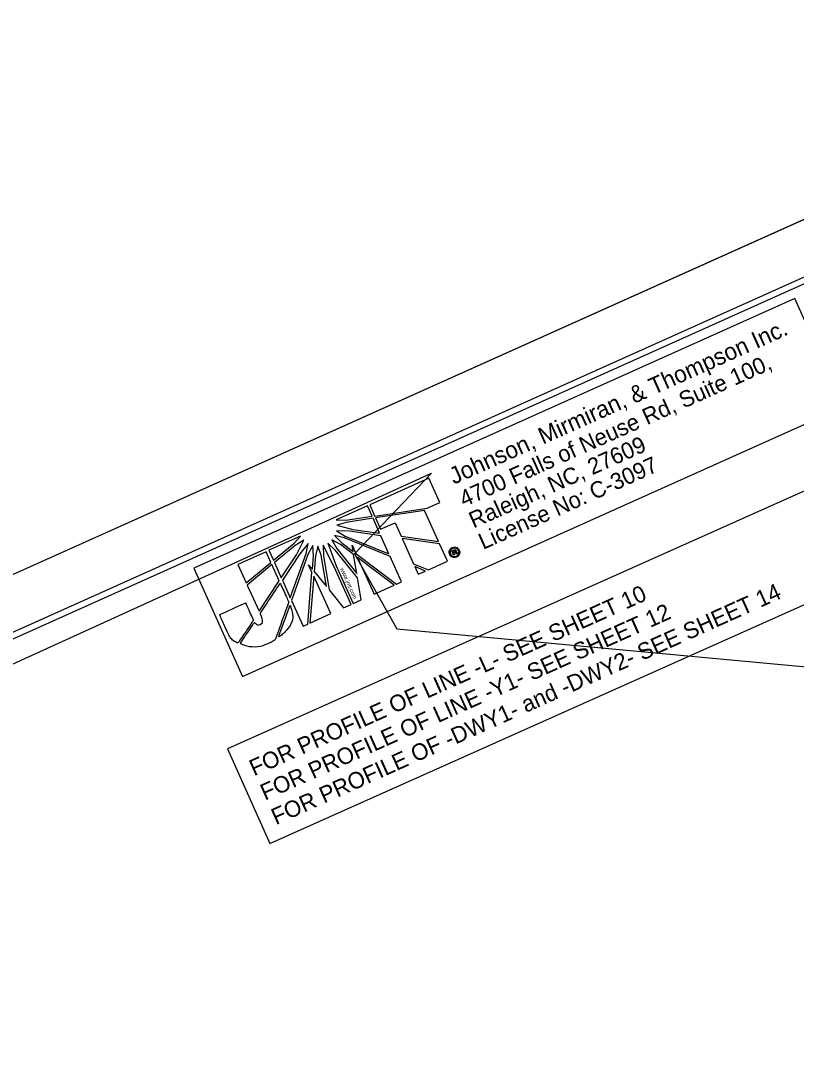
# Model space of a CAD drawing. Extents: x 553939 to 555925, y 502653 to 504347.
# Drawn here: x 554953.8 to 555283.4, y 503904.2 to 504346.6 of the extents above; entities that cross this region are included whole.
import ezdxf

# ---------------------------------------------------------------- set-up
doc = ezdxf.new("R2010")
doc.units = 0
for name, color, linetype in [('Prop Horizontal Alignment Curve and Spiral Data', 7, 'Continuous'), ('Prop Horizontal Alignment Direction Label', 7, 'Continuous'), ('Prop SS Cut Line', 7, 'Continuous'), ('Prop SS Fill Line', 7, 'Continuous'), ('Prop SS Transition Line', 7, 'Continuous'), ('Scratch_Level_9', 7, 'Continuous'), ('Sheet Clip Boundary CELL', 7, 'Continuous')]:
    doc.layers.add(name, color=color, linetype=linetype)

msp = doc.modelspace()

# ---------------------------------------------------------------- linework, layer by layer
at = {"layer": 'Prop Horizontal Alignment Curve and Spiral Data'}
msp.add_lwpolyline([(555041.64, 504036.97), (555059.67, 503996.82), (555333.29, 504119.14), (555315.26, 504159.3), (555041.64, 504036.97)], dxfattribs=at)
at = {"layer": 'Prop Horizontal Alignment Direction Label'}
msp.add_lwpolyline([(555474.87, 504346.62), (553938.64, 503656.8), (554389.23, 502653.32), (555925.47, 503343.14)], close=True, dxfattribs=at)
at = {"layer": 'Prop SS Cut Line'}
msp.add_lwpolyline([(555469.6, 504316.85), (554101.23, 503702.4), (554531.34, 502744.54), (555899.72, 503358.98)], close=True, dxfattribs=at)
at = {"layer": 'Prop SS Fill Line'}
msp.add_lwpolyline([(555479.96, 504324.29), (553959.7, 503641.65), (554391.9, 502679.13), (555912.16, 503361.78)], close=True, dxfattribs=at)
at = {"layer": 'Prop SS Transition Line'}
for p, q in [((555127.25, 504152.07), (555102.12, 504140.76)), ((555131.88, 504141.78), (555127.25, 504152.07)), ((555126.54, 504139.37), (555131.88, 504141.78)), ((555101.22, 504140.29), (555087.94, 504134.38)), ((555103.16, 504135.99), (555101.22, 504140.29)), ((555102.12, 504140.76), (555104.2, 504136.15)), ((555104.26, 504136.01), (555126.54, 504139.37)), ((555125.48, 504138.35), (555104.58, 504135.3)), ((555131.42, 504125.16), (555125.48, 504138.35)), ((555087.94, 504134.38), (555092.01, 504134.31)), ((555092.06, 504133.29), (555088.16, 504132.11)), ((555092.01, 504134.31), (555103.16, 504135.99)), ((555103.57, 504135.08), (555092.06, 504133.29)), ((555106.34, 504128.72), (555103.57, 504135.08)), ((555104.2, 504136.15), (555104.26, 504136.01)), ((555104.58, 504135.3), (555104.62, 504135.22)), ((555104.62, 504135.22), (555106.78, 504130.41)), ((555106.78, 504130.41), (555112.92, 504133.17)), ((555112.92, 504133.17), (555115.5, 504127.43)), ((555087.95, 504129.78), (555091.74, 504127.53)), ((555093.6, 504129.55), (555087.95, 504129.78)), ((555088.16, 504132.11), (555095.02, 504130.26)), ((555106.82, 504127.65), (555093.6, 504129.55)), ((555095.02, 504130.26), (555106.34, 504128.72)), ((555072.72, 504127.53), (555059.27, 504121.47)), ((555061.2, 504117.19), (555069.97, 504124.46)), ((555069.97, 504124.46), (555072.72, 504127.53)), ((555074.08, 504125.77), (555070.39, 504123.54)), ((555070.94, 504119.52), (555074.08, 504125.77)), ((555075.9, 504124.36), (555072.38, 504120)), ((555075.05, 504120.09), (555075.9, 504124.36)), ((555084.31, 504124.49), (555087.94, 504114.79)), ((555087.61, 504121.37), (555084.31, 504124.49)), ((555085.98, 504125.88), (555088.1, 504122.24)), ((555089.66, 504123.89), (555085.98, 504125.88)), ((555087.2, 504127.71), (555090.38, 504124.54)), ((555091.47, 504126.7), (555087.2, 504127.71)), ((555090.38, 504124.54), (555095.08, 504120.95)), ((555110.82, 504118.76), (555091.47, 504126.7)), ((555091.74, 504127.53), (555110.26, 504120)), ((555110.26, 504120), (555106.82, 504127.65)), ((555115.5, 504127.43), (555131.42, 504125.16)), ((555115.94, 504126.45), (555120.76, 504115.76)), ((555131.84, 504124.23), (555115.94, 504126.45)), ((555135.17, 504116.82), (555131.84, 504124.23)), ((555058.05, 504120.85), (555046.1, 504115.47)), ((555060.13, 504116.24), (555058.05, 504120.85)), ((555059.27, 504121.47), (555061.2, 504117.19)), ((555070.39, 504123.54), (555061.61, 504116.27)), ((555064.53, 504109.8), (555070.94, 504119.52)), ((555072.38, 504120), (555065, 504108.75)), ((555068.35, 504101.3), (555075.05, 504120.09)), ((555075.86, 504119.67), (555068.92, 504100.04)), ((555077.93, 504123.54), (555075.86, 504119.67)), ((555078.19, 504119.06), (555077.93, 504123.54)), ((555080.12, 504123.25), (555079.13, 504119.14)), ((555081.45, 504119.41), (555080.12, 504123.25)), ((555087.09, 504114.41), (555082.34, 504123.6)), ((555082.34, 504123.6), (555082.42, 504119.04)), ((555096.94, 504109.81), (555087.61, 504121.37)), ((555088.1, 504122.24), (555096.63, 504111.56)), ((555095.27, 504119.68), (555089.66, 504123.89)), ((555095.08, 504120.95), (555094.63, 504123.59)), ((555094.63, 504123.59), (555096.2, 504120.1)), ((555096.63, 504111.56), (555095.27, 504119.68)), ((555096.2, 504120.1), (555113.54, 504107.08)), ((555136.99, 504121.19), (555137.74, 504121.53)), ((555137.81, 504119.36), (555136.99, 504121.19)), ((555137.25, 504122.6), (555137.42, 504122.22)), ((555137.42, 504122.22), (555137.25, 504122.6)), ((555137.89, 504121.18), (555137.56, 504121.03)), ((555137.56, 504121.03), (555137.76, 504120.59)), ((555137.74, 504121.53), (555137.85, 504121.58)), ((555137.74, 504121.53), (555137.89, 504121.18)), ((555137.89, 504121.18), (555137.74, 504121.53)), ((555137.76, 504120.59), (555138.09, 504120.74)), ((555138.23, 504119.55), (555137.81, 504119.36)), ((555137.94, 504121.2), (555137.89, 504121.18)), ((555138.24, 504120.41), (555137.91, 504120.26)), ((555137.91, 504120.26), (555138.23, 504119.55)), ((555138.09, 504120.74), (555138.11, 504120.75)), ((555138.09, 504120.74), (555138.24, 504120.41)), ((555138.24, 504120.41), (555138.09, 504120.74)), ((555138.25, 504120.42), (555138.24, 504120.41)), ((555046.1, 504115.47), (555049.67, 504107.55)), ((555049.67, 504107.55), (555060.13, 504116.24)), ((555060.52, 504115.37), (555050.08, 504106.64)), ((555063.64, 504108.45), (555060.52, 504115.37)), ((555061.61, 504116.27), (555064.53, 504109.8)), ((555077.59, 504112.12), (555076.17, 504115.28)), ((555076.17, 504115.28), (555077.74, 504113.37)), ((555077.74, 504113.37), (555078.19, 504119.06)), ((555079.13, 504119.14), (555078.58, 504112.4)), ((555083.72, 504106.08), (555081.45, 504119.41)), ((555082.42, 504119.04), (555084.86, 504104.61)), ((555112.53, 504106.69), (555096.97, 504118.38)), ((555096.97, 504118.38), (555103.97, 504102.84)), ((555115.65, 504108.03), (555110.82, 504118.76)), ((555120.76, 504115.76), (555127.07, 504113.17)), ((555127.07, 504113.17), (555135.17, 504116.82)), ((555138.88, 504118.98), (555138.9, 504118.99)), ((555138.88, 504118.98), (555139.06, 504118.59)), ((555139.06, 504118.59), (555138.88, 504118.98)), ((555139.08, 504118.59), (555139.06, 504118.59)), ((555075.78, 504090.08), (555077.59, 504112.12)), ((555078.58, 504112.4), (555083.72, 504106.08)), ((555094.27, 504098.47), (555087.09, 504114.41)), ((555087.94, 504114.79), (555095.11, 504098.85)), ((555125.88, 504112.64), (555121.28, 504114.59)), ((555121.28, 504114.59), (555122.79, 504111.24)), ((555122.79, 504111.24), (555125.88, 504112.64)), ((555050.08, 504106.64), (555055.1, 504095.5)), ((555055.1, 504095.5), (555063.64, 504108.45)), ((555065, 504108.75), (555068.35, 504101.3)), ((555078.36, 504110.41), (555076.7, 504090.5)), ((555085.62, 504094.51), (555078.36, 504110.41)), ((555098.43, 504100.35), (555096.94, 504109.81)), ((555103.97, 504102.84), (555112.53, 504106.69)), ((555113.54, 504107.08), (555115.65, 504108.03)), ((555084.86, 504104.61), (555090.99, 504097)), ((555068.92, 504100.04), (555073.8, 504089.19)), ((555090.99, 504097), (555094.27, 504098.47)), ((555095.11, 504098.85), (555098.43, 504100.35)), ((555076.7, 504090.5), (555085.62, 504094.51)), ((555073.8, 504089.19), (555075.78, 504090.08))]:
    msp.add_line(p, q, dxfattribs=at)
msp.add_lwpolyline([(555048.1, 504067.77), (555303.57, 504182.49), (555282.87, 504228.59), (555027.39, 504113.87)], close=True, dxfattribs=at)
for points in [[(555127.25, 504152.07), (555102.12, 504140.76), (555104.2, 504136.15), (555104.26, 504136.01), (555126.54, 504139.37), (555131.88, 504141.78), (555127.25, 504152.07)], [(555092.01, 504134.31), (555103.16, 504135.99), (555101.22, 504140.29), (555087.94, 504134.38), (555092.01, 504134.31)], [(555104.58, 504135.3), (555104.62, 504135.22), (555106.78, 504130.41), (555112.92, 504133.17), (555115.5, 504127.43), (555131.42, 504125.16), (555125.48, 504138.35), (555104.58, 504135.3)], [(555088.16, 504132.11), (555095.02, 504130.26), (555106.34, 504128.72), (555103.57, 504135.08), (555092.06, 504133.29), (555088.16, 504132.11)], [(555087.95, 504129.78), (555091.74, 504127.53), (555110.26, 504120), (555106.82, 504127.65), (555093.6, 504129.55), (555087.95, 504129.78)], [(555069.97, 504124.46), (555072.72, 504127.53), (555059.27, 504121.47), (555061.2, 504117.19), (555069.97, 504124.46)], [(555061.61, 504116.27), (555064.53, 504109.8), (555070.94, 504119.52), (555074.08, 504125.77), (555070.39, 504123.54), (555061.61, 504116.27)], [(555065, 504108.75), (555068.35, 504101.3), (555075.05, 504120.09), (555075.9, 504124.36), (555072.38, 504120), (555065, 504108.75)], [(555084.31, 504124.49), (555087.94, 504114.79), (555095.11, 504098.85), (555098.43, 504100.35), (555096.94, 504109.81), (555087.61, 504121.37), (555084.31, 504124.49)], [(555085.98, 504125.88), (555088.1, 504122.24), (555096.63, 504111.56), (555095.27, 504119.68), (555089.66, 504123.89), (555085.98, 504125.88)], [(555087.2, 504127.71), (555090.38, 504124.54), (555095.08, 504120.95), (555094.63, 504123.59), (555096.2, 504120.1), (555113.54, 504107.08), (555115.65, 504108.03), (555110.82, 504118.76), (555091.47, 504126.7), (555087.2, 504127.71)], [(555115.94, 504126.45), (555120.76, 504115.76), (555127.07, 504113.17), (555135.17, 504116.82), (555131.84, 504124.23), (555115.94, 504126.45), (555115.94, 504126.45)], [(555049.67, 504107.55), (555060.13, 504116.24), (555058.05, 504120.85), (555046.1, 504115.47), (555049.67, 504107.55)], [(555077.93, 504123.54), (555075.86, 504119.67), (555068.92, 504100.04), (555073.8, 504089.19), (555075.78, 504090.08), (555077.59, 504112.12), (555076.17, 504115.28), (555077.74, 504113.37), (555078.19, 504119.06), (555077.93, 504123.54)], [(555080.12, 504123.25), (555079.13, 504119.14), (555078.58, 504112.4), (555083.72, 504106.08), (555081.45, 504119.41), (555080.12, 504123.25)], [(555082.42, 504119.04), (555084.86, 504104.61), (555090.99, 504097), (555094.27, 504098.47), (555087.09, 504114.41), (555082.34, 504123.6), (555082.42, 504119.04)], [(555139.16, 504120.49), (555139.21, 504120.39), (555139.25, 504120.33), (555139.28, 504120.26), (555139.42, 504120.09), (555139.04, 504119.92)], [(555055.1, 504095.5), (555063.64, 504108.45), (555060.52, 504115.37), (555050.08, 504106.64), (555055.1, 504095.5)], [(555103.97, 504102.84), (555112.53, 504106.69), (555096.97, 504118.38), (555103.97, 504102.84)], [(555122.79, 504111.24), (555122.79, 504111.24), (555125.88, 504112.64), (555121.28, 504114.59), (555122.79, 504111.24)], [(555076.7, 504090.5), (555085.62, 504094.51), (555078.36, 504110.41), (555076.7, 504090.5)]]:
    msp.add_lwpolyline(points, dxfattribs=at)
for points, degree in [([(555139.06, 504118.59), (555138.51, 504118.34), (555137.94, 504118.32), (555137.36, 504118.54), (555136.79, 504118.74), (555136.38, 504119.13), (555136.12, 504119.7), (555135.87, 504120.26), (555135.85, 504120.84), (555136.08, 504121.38), (555136.31, 504121.94), (555136.69, 504122.35), (555137.25, 504122.6)], 3), ([(555137.42, 504122.22), (555136.97, 504122.02), (555136.66, 504121.7), (555136.48, 504121.26), (555136.31, 504120.8), (555136.32, 504120.33), (555136.52, 504119.88), (555136.72, 504119.43), (555137.07, 504119.11), (555137.53, 504118.93), (555137.98, 504118.76), (555138.43, 504118.78), (555138.88, 504118.98)], 3), ([(555137.25, 504122.6), (555137.82, 504122.86), (555138.39, 504122.88), (555138.96, 504122.67), (555139.52, 504122.49), (555139.94, 504122.1), (555140.19, 504121.53)], 3), ([(555138.9, 504118.99), (555139.35, 504119.19), (555139.66, 504119.51), (555139.83, 504119.97), (555140.01, 504120.43), (555139.99, 504120.9), (555139.79, 504121.35), (555139.59, 504121.8), (555139.24, 504122.12), (555138.79, 504122.3), (555138.34, 504122.45), (555137.89, 504122.43), (555137.42, 504122.22)], 3), ([(555137.85, 504121.58), (555138.32, 504121.79), (555138.63, 504121.71), (555138.8, 504121.34), (555138.87, 504121.18), (555138.87, 504121.01), (555138.76, 504120.85)], 3), ([(555138.11, 504120.75), (555138.37, 504120.87), (555138.47, 504121.01), (555138.4, 504121.16), (555138.34, 504121.3), (555138.19, 504121.31), (555137.94, 504121.2)], 3), ([(555138.6, 504120.5), (555138.54, 504120.51), (555138.42, 504120.49), (555138.25, 504120.42)], 2), ([(555139.04, 504119.92), (555138.95, 504119.99), (555138.87, 504120.08), (555138.81, 504120.21), (555138.73, 504120.38), (555138.67, 504120.47), (555138.6, 504120.5)], 3), ([(555138.76, 504120.85), (555138.91, 504120.83), (555139.04, 504120.71), (555139.16, 504120.49)], 2), ([(555140.19, 504121.53), (555140.45, 504120.97), (555140.46, 504120.4), (555140.26, 504119.83), (555140.03, 504119.26), (555139.64, 504118.85), (555139.08, 504118.59)], 3), ([(555055.56, 504089.89), (555054.85, 504089.57), (555054.06, 504089.69), (555053.21, 504090.9), (555053.21, 504090.9), (555047.02, 504081.73), (555047.02, 504081.73), (555050.91, 504080.14), (555055.88, 504080.38), (555059.45, 504081.99), (555060.37, 504082.41), (555061.05, 504082.81), (555061.94, 504083.45), (555061.94, 504083.45), (555067.7, 504099.42), (555067.7, 504099.42), (555067.7, 504099.42), (555064.08, 504107.46), (555064.08, 504107.46), (555064.08, 504107.46), (555055.55, 504094.49), (555055.55, 504094.49), (555056.91, 504091.47), (555056.54, 504090.34), (555055.56, 504089.89)], 3), ([(555055.56, 504089.89), (555054.85, 504089.57), (555054.06, 504089.69), (555053.21, 504090.9), (555053.21, 504090.9), (555047.02, 504081.73), (555047.02, 504081.73), (555050.91, 504080.14), (555055.88, 504080.38), (555059.45, 504081.99), (555060.37, 504082.41), (555061.05, 504082.81), (555061.94, 504083.45), (555061.94, 504083.45), (555067.7, 504099.42), (555067.7, 504099.42), (555067.7, 504099.42), (555064.08, 504107.46), (555064.08, 504107.46), (555064.08, 504107.46), (555055.55, 504094.49), (555055.55, 504094.49), (555056.91, 504091.47), (555056.54, 504090.34), (555055.56, 504089.89)], 3), ([(555049.36, 504099.08), (555049.36, 504099.08), (555038.29, 504094.1), (555038.29, 504094.1), (555038.29, 504094.1), (555041.41, 504087.18), (555041.41, 504087.18), (555041.41, 504087.18), (555041.74, 504086.45), (555041.74, 504086.45), (555042.72, 504084.28), (555044.2, 504082.88), (555046.11, 504082.01), (555046.11, 504082.01), (555052.71, 504091.63), (555052.65, 504091.76), (555052.65, 504091.76), (555049.36, 504099.08), (555049.36, 504099.08)], 3), ([(555068.27, 504098.16), (555068.27, 504098.16), (555063.29, 504084.36), (555063.29, 504084.36), (555067.34, 504087.54), (555070.51, 504092.6), (555068.27, 504098.16)], 3)]:
    msp.add_open_spline(points, degree=degree, dxfattribs=at)
at = {"layer": 'Scratch_Level_9'}
msp.add_line((555474.87, 504346.62), (553938.64, 503656.8), dxfattribs=at)
at = {"layer": 'Sheet Clip Boundary CELL'}
msp.add_lwpolyline([(554122.43, 503695.68), (555128.42, 504154.2), (555095.7, 504120), (555113.65, 504088.12), (555364.03, 504064.84), (555538.05, 504147.98), (555542.54, 504077.37), (555561.42, 504000.98), (555610.11, 503951.13), (555644.95, 503906.87), (555662.42, 503867.97), (555642.54, 503853.07), (555814.87, 503478.7), (555868.57, 503357.36), (555699.98, 503280.3), (555094.66, 503015.3), (554864.55, 502951)], dxfattribs=at)
msp.add_lwpolyline([(555608.35, 503927.62), (555814.87, 503478.7), (555868.57, 503357.36), (555699.98, 503280.3), (555094.66, 503015.3), (554759.27, 502917.8), (554683.01, 502878.56), (554582.25, 502838.31), (554549.81, 502954), (554532.1, 502969.19), (554525.96, 503000.02), (554442.4, 502999.26), (554417.71, 503015.86), (554346.87, 503170.59), (554325.2, 503273.41), (554285.23, 503305.85), (554122.43, 503695.68), (555128.42, 504154.2), (555095.7, 504120), (555113.65, 504088.12), (555364.03, 504064.84), (555538.05, 504147.98), (555542.54, 504077.37), (555561.42, 504000.98)], close=True, dxfattribs=at)

# ---------------------------------------------------------------- texts
at = {"layer": 'Prop Horizontal Alignment Curve and Spiral Data'}
for s, p in [('FOR PROFILE OF LINE -L- SEE SHEET 10', (555052.95, 504025.29)), ('FOR PROFILE OF -DWY1- and -DWY2- SEE SHEET 14', (555062.27, 504004.54)), ('FOR PROFILE OF LINE -Y1- SEE SHEET 12', (555057.61, 504014.92))]:
    msp.add_text(s, height=7, rotation=24.1816, dxfattribs=at).set_placement(p)
at = {"layer": 'Prop SS Transition Line'}
for s, height, rotation, p in [('Johnson, Mirmiran, & Thompson Inc.', 7.1557, 24.1816, (555137.91, 504149.31)), ('4700 Falls of Neuse Rd, Suite 100, ', 6.9512, 24.1816, (555142.21, 504139.73)), ('Raleigh, NC, 27609', 6.9512, 24.1816, (555146.28, 504130.67)), ('License No: C-3097', 6.9512, 24.1816, (555150.35, 504121.6)), ('www.jmt.com', 1.7378, 294.1816, (555089.47, 504113.53))]:
    msp.add_text(s, height=height, rotation=rotation, dxfattribs=at).set_placement(p)

doc.saveas('drawing.dxf')
